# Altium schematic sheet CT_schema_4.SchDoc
size 144 x 123 mm
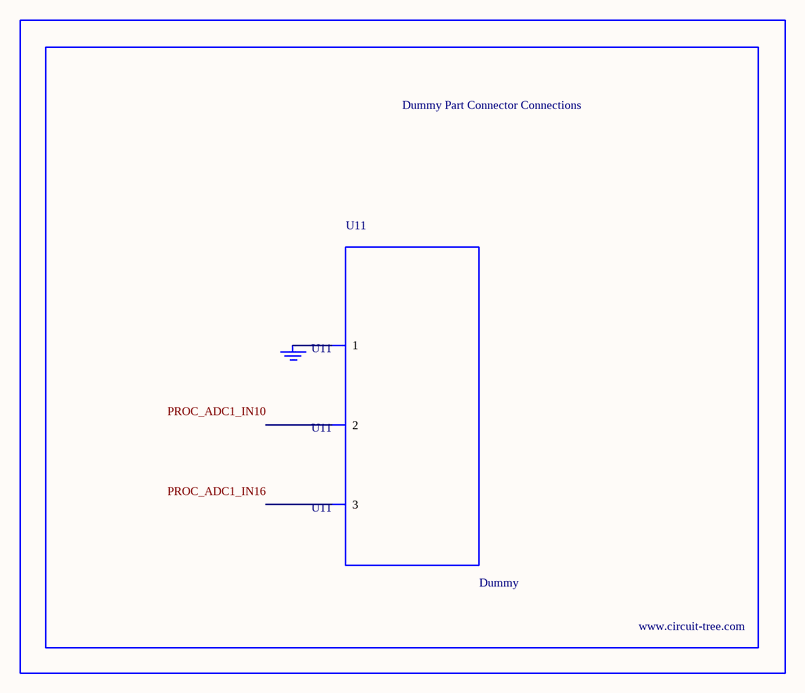
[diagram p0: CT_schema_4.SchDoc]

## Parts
BORDER3  (no value)
GND_INSTANCE_3_0  (no value)
U11  Dummy  [DUMMY_PACKAGE_111]

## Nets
NetGND_INSTANCE_3_0_0: GND_INSTANCE_3_0.0(GND) U11.1

Not connected (* = marked no-connect by the designer): U11 2 3

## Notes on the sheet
- Labels drawn without touching a wire or pin: PROC_ADC1_IN10, PROC_ADC1_IN16

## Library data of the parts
BORDER3 = BORDER_PAGE3
GND_INSTANCE_3_0 = GND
